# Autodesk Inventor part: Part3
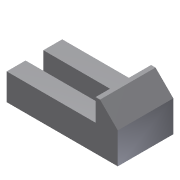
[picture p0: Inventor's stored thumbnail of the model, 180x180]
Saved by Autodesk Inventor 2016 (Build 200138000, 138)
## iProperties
Shininess: 77.0
Length Units: 11269
Angle Units: 11279
Time Units: 11290
Mass Units: 11283
Length Display Precision: 3
Angle Display Precision: 2
Created: 2002-01
Part Number: Part3
Document SubType Name: Modeling
Designer: ***
Density: 1 g/cm^3
Material: Generic
Appearance: Default
Density: 0.0
Volumn: 0.0
Area: 0.0
PropertySet Name: Model Information
Control State: 0
Master: False
Checked Out: False
Author: ***
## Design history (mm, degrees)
sketch "Sketch2"
  geometry: L1 (23.289, -5.477)-(-16.711, -5.477); L2 (-16.711, -5.477)-(-16.711, 4.523); L3 (-16.711, 4.523)-(-18.711, 4.523); L4 (-18.711, 4.523)-(-26.711, -3.477); L5 (-26.711, -3.477)-(-26.711, -17.477); L6 (-26.711, -17.477)-(23.289, -17.477); L7 (23.289, -17.477)-(23.289, -5.477)
  constraints: 14 end point, 4 parallel, 1 horizontal, 1 perpendicular
  dimensions: "d0" = 50 distance of L5.end L6.end; "d1" = 12 distance of L6.end L1.start; "d2" = 22 distance between parallel lines of L3 L6; "d3" = 135 deg angle of L5 L4; "d4" = 2 distance of L2.end L3.end; "d5" = 40 distance of L1.start L1.end
extrude "Extrusion1" new body sketch "Sketch2" stored distance "d6" = 25; taper "d7" = 0 deg
sketch "Sketch3"
  geometry: L1 (-4, -8.5)-(36, -8.5); L2 (36, -8.5)-(36, -16.5); L3 (36, -16.5)-(-4, -16.5); L4 (-4, -16.5)-(-4, -8.5); L5 (40, -25)-(40, 0) reference; L6 (40, 0)-(0, 0) reference
  constraints: 8 end point, 2 parallel, 1 horizontal, 1 perpendicular
  dimensions: "d8" = 8 distance of L1.end L2.end; "d9" = 40 distance of L1.start L1.end; "d10" = 4 distance between parallel lines of L5 L2; "d11" = 8.5 distance between parallel lines of L6 L1
extrude "Extrusion2" cut sketch "Sketch3" stored distance "d12" = 25; taper "d13" = 0 deg
body "Solid1"
